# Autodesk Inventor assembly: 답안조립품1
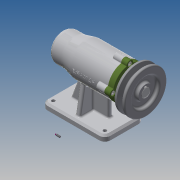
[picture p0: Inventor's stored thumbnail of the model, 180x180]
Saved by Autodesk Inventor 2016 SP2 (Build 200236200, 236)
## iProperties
Created: 2019-07
Part Number: 답안조립품1
Document SubType Name: Assembly
Designer: EZ
Author: EZ
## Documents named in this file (12)
- X:\490704V1075 윤채성\답안조립품1.iam
- X:\490704V1075 윤채성\본체.ipt
- X:\490704V1075 윤채성\V벨트풀리.ipt
- X:\490704V1075 윤채성\멈춤나사 M3.ipt
- X:\490704V1075 윤채성\베어링 6004.ipt
- X:\490704V1075 윤채성\베어링 51202.ipt
- X:\490704V1075 윤채성\볼트 M4.ipt
- X:\490704V1075 윤채성\어댑터슬리브.ipt
- X:\490704V1075 윤채성\오일 실.ipt
- X:\490704V1075 윤채성\축.ipt
- X:\490704V1075 윤채성\커버.ipt
- X:\490704V1075 윤채성\키 5 x 5 x 16.ipt
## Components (1 placed, 1 different names)
1. V벨트풀리:1
